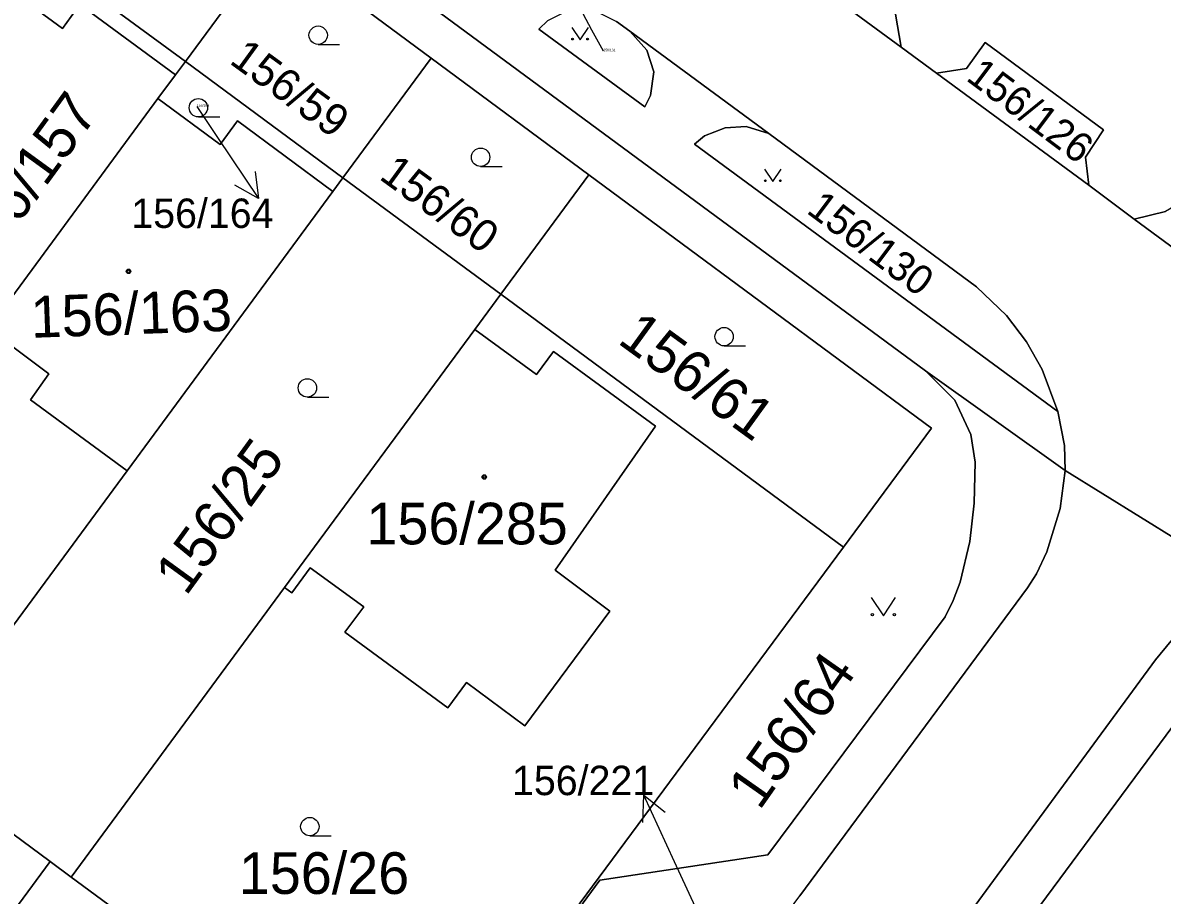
# Model space of a CAD drawing. Extents: x -598233 to -596890, y -1157848 to -1156431.
# Drawn here: x -597550.15 to -597503.64, y -1156840.44 to -1156804.85 of the extents above; entities that cross this region are included whole.
import ezdxf

# ---------------------------------------------------------------- set-up
doc = ezdxf.new("R2010")
doc.units = 0
for name, color, linetype in [('Level 1', 7, 'Continuous'), ('Level 4', 7, 'Continuous'), ('Level 5', 7, 'Continuous'), ('Level 57', 7, 'Continuous'), ('Level 60', 7, 'Continuous')]:
    doc.layers.add(name, color=color, linetype=linetype)

msp = doc.modelspace()

# ---------------------------------------------------------------- linework, layer by layer
at = {"layer": 'Level 1'}
for points in [[(-597675.04, -1156699.81), (-597644.05, -1156722.64), (-597605.82, -1156750.84), (-597563.45, -1156782.09), (-597513.3, -1156819.05)], [(-597514.3, -1156805.85), (-597514.52, -1156804.5), (-597514.27, -1156803.47), (-597508.33, -1156795.09), (-597496.6, -1156803.39), (-597502.59, -1156812.02), (-597503.51, -1156812.55), (-597504.78, -1156812.86)], [(-597539.9, -1156801.53), (-597543.51, -1156806.43)], [(-597539.9, -1156801.53), (-597533.48, -1156806.29)], [(-597543.51, -1156806.43), (-597549.95, -1156801.69)], [(-597514.3, -1156805.85), (-597518.43, -1156802.8)], [(-597551.07, -1156803.21), (-597548.53, -1156805.08), (-597547.82, -1156804.11), (-597543.91, -1156806.97)], [(-597525.37, -1156805.19), (-597524.67, -1156805.96), (-597524.39, -1156806.85), (-597524.53, -1156807.82), (-597524.76, -1156808.28), (-597529.08, -1156805.11), (-597528.72, -1156804.75), (-597527.9, -1156804.35), (-597526.79, -1156804.36), (-597525.92, -1156804.8)], [(-597525.92, -1156804.8), (-597525.37, -1156805.19)], [(-597519.7, -1156809.37), (-597525.37, -1156805.19)], [(-597512.85, -1156806.91), (-597511.63, -1156806.72), (-597510.87, -1156805.65), (-597506.04, -1156809.22), (-597506.77, -1156810.33), (-597506.64, -1156811.48)], [(-597512.85, -1156806.91), (-597514.3, -1156805.85)], [(-597543.51, -1156806.43), (-597543.91, -1156806.97)], [(-597537.08, -1156811.18), (-597543.51, -1156806.43)], [(-597533.48, -1156806.29), (-597537.08, -1156811.18)], [(-597533.48, -1156806.29), (-597527.04, -1156811.05)], [(-597544.63, -1156807.94), (-597543.91, -1156806.97)], [(-597506.64, -1156811.48), (-597512.85, -1156806.91)], [(-597552.26, -1156818.3), (-597544.63, -1156807.94)], [(-597537.49, -1156811.73), (-597541.38, -1156808.85), (-597542.09, -1156809.81), (-597544.63, -1156807.94)], [(-597519.7, -1156809.37), (-597520.62, -1156809.08), (-597521.48, -1156809.14), (-597522.32, -1156809.46), (-597522.73, -1156809.8), (-597507.9, -1156820.71)], [(-597507.9, -1156820.71), (-597508.54, -1156819), (-597509.18, -1156817.86), (-597509.99, -1156816.79), (-597511.22, -1156815.62), (-597519.7, -1156809.37)], [(-597537.49, -1156811.73), (-597537.08, -1156811.18)], [(-597530.64, -1156815.92), (-597537.08, -1156811.18)], [(-597530.64, -1156815.92), (-597527.04, -1156811.05)], [(-597527.04, -1156811.05), (-597513.06, -1156821.39), (-597516.65, -1156826.24)], [(-597545.89, -1156823.13), (-597537.49, -1156811.73)], [(-597504.78, -1156812.86), (-597506.64, -1156811.48)], [(-597500.61, -1156815.94), (-597504.78, -1156812.86)], [(-597531.7, -1156817.36), (-597530.64, -1156815.92)], [(-597516.65, -1156826.24), (-597530.64, -1156815.92)], [(-597531.7, -1156817.36), (-597529.18, -1156819.2), (-597528.48, -1156818.26), (-597524.32, -1156821.31), (-597528.42, -1156827.18), (-597526.19, -1156828.85), (-597529.65, -1156833.53), (-597532.04, -1156831.77), (-597532.8, -1156832.8), (-597537, -1156829.71), (-597536.23, -1156828.68), (-597538.41, -1156827.08), (-597539.17, -1156828.1), (-597539.46, -1156827.89)], [(-597539.46, -1156827.89), (-597531.7, -1156817.36)], [(-597552.26, -1156818.3), (-597552.14, -1156818.49), (-597551.38, -1156817.46), (-597549.08, -1156819.17), (-597549.83, -1156820.23), (-597545.89, -1156823.13)], [(-597549.31, -1156878.82), (-597548.81, -1156877.83), (-597548.51, -1156877.13), (-597548.17, -1156876.19), (-597548.03, -1156875.41), (-597548, -1156874.67), (-597548.22, -1156869.23), (-597526.59, -1156839.83), (-597519.73, -1156838.79), (-597512.5, -1156829.08), (-597512.17, -1156828.42), (-597511.88, -1156827.67), (-597511.49, -1156826.01), (-597511.31, -1156824.45), (-597511.28, -1156822.78), (-597511.45, -1156821.65), (-597512.11, -1156820.25), (-597513.3, -1156819.05)], [(-597513.3, -1156819.05), (-597507.6, -1156823.12)], [(-597507.6, -1156823.12), (-597507.63, -1156822.1), (-597507.9, -1156820.71)], [(-597554.61, -1156834.95), (-597545.89, -1156823.13)], [(-597507.6, -1156823.12), (-597507.81, -1156824.66), (-597508.35, -1156826.43), (-597508.77, -1156827.33), (-597509.14, -1156827.9), (-597518.43, -1156840.47)], [(-597507.6, -1156823.12), (-597499.92, -1156827.88)], [(-597534.23, -1156849.98), (-597516.65, -1156826.24)], [(-597548.17, -1156839.7), (-597539.46, -1156827.89)], [(-597514.13, -1156844.75), (-597503.91, -1156830.84), (-597503.28, -1156830.06), (-597502.2, -1156829.07), (-597500.85, -1156828.25), (-597499.92, -1156827.88)], [(-597502.47, -1156832.55), (-597511.93, -1156845.32), (-597510.88, -1156852.31), (-597512.21, -1156854.11)], [(-597554.61, -1156834.95), (-597549.03, -1156839.07)], [(-597566.94, -1156863.37), (-597549.03, -1156839.07)], [(-597549.03, -1156839.07), (-597548.17, -1156839.7)], [(-597548.17, -1156839.7), (-597534.23, -1156849.98)]]:
    msp.add_lwpolyline(points, dxfattribs=at)
at = {"layer": 'Level 5'}
for p, q in [((-597538.09, -1156805.73), (-597537.215, -1156805.73)), ((-597542.98, -1156808.69), (-597542.105, -1156808.69)), ((-597531.46, -1156810.71), (-597530.585, -1156810.71)), ((-597521.52, -1156818.03), (-597520.645, -1156818.03)), ((-597538.53, -1156820.12), (-597537.655, -1156820.12)), ((-597538.43, -1156838.02), (-597537.555, -1156838.02))]:
    msp.add_line(p, q, dxfattribs=at)
for points in [[(-597527.741, -1156805.04), (-597527.4, -1156805.55), (-597527.06, -1156805.04)], [(-597519.871, -1156810.82), (-597519.53, -1156811.33), (-597519.19, -1156810.82)], [(-597515.521, -1156828.3), (-597515.02, -1156829.05), (-597514.52, -1156828.3)]]:
    msp.add_lwpolyline(points, dxfattribs=at)
for centre, radius in [((-597538.09, -1156805.355), 0.375), ((-597527.706, -1156805.516), 0.034), ((-597527.095, -1156805.516), 0.034), ((-597542.98, -1156808.315), 0.375), ((-597531.46, -1156810.335), 0.375), ((-597519.836, -1156811.296), 0.034), ((-597519.225, -1156811.296), 0.034), ((-597545.83, -1156814.99), 0.09), ((-597545.83, -1156814.99), 0.0521), ((-597521.52, -1156817.655), 0.375), ((-597538.53, -1156819.745), 0.375), ((-597531.31, -1156823.38), 0.09), ((-597531.31, -1156823.38), 0.0521), ((-597515.47, -1156829), 0.05), ((-597514.571, -1156829), 0.05), ((-597538.43, -1156837.645), 0.375)]:
    msp.add_circle(centre, radius, dxfattribs=at)
at = {"layer": 'Level 57'}
for p, q in [((-597526.915, -1156805.144), (-597528.333, -1156802.5)), ((-597526.45, -1156806.01), (-597526.915, -1156805.144)), ((-597543.04, -1156808.27), (-597542.196, -1156809.529)), ((-597542.196, -1156809.529), (-597540.525, -1156812.02)), ((-597523.543, -1156839.083), (-597524.803, -1156836.36)), ((-597521.93, -1156842.57), (-597523.543, -1156839.083))]:
    msp.add_line(p, q, dxfattribs=at)
for points in [[(-597540.667, -1156810.911), (-597540.525, -1156812.02), (-597541.497, -1156811.468)], [(-597524.836, -1156837.478), (-597524.803, -1156836.36), (-597523.929, -1156837.058)]]:
    msp.add_lwpolyline(points, dxfattribs=at)
at = {"layer": 'Level 60'}
for points in [[(-597563.45, -1156782.09), (-597513.3, -1156819.05), (-597512.11, -1156820.25), (-597511.45, -1156821.65), (-597511.28, -1156822.78), (-597511.31, -1156824.45), (-597511.49, -1156826.01), (-597511.88, -1156827.67), (-597512.17, -1156828.42), (-597512.5, -1156829.08), (-597519.73, -1156838.79), (-597526.59, -1156839.83), (-597548.22, -1156869.23), (-597548, -1156874.67), (-597548.03, -1156875.41), (-597548.17, -1156876.19), (-597548.51, -1156877.13), (-597548.81, -1156877.83), (-597549.31, -1156878.82), (-597550.49, -1156878.9)], [(-597528.72, -1156804.75), (-597529.08, -1156805.11), (-597524.76, -1156808.28), (-597524.53, -1156807.82), (-597524.39, -1156806.85), (-597524.67, -1156805.96), (-597525.37, -1156805.19), (-597519.7, -1156809.37), (-597520.62, -1156809.08), (-597521.48, -1156809.14), (-597522.32, -1156809.46), (-597522.73, -1156809.8), (-597507.9, -1156820.71), (-597507.63, -1156822.1), (-597507.6, -1156823.12), (-597513.3, -1156819.05), (-597563.45, -1156782.09)], [(-597552.94, -1156875.36), (-597534.23, -1156849.98), (-597516.65, -1156826.24), (-597513.06, -1156821.39), (-597527.04, -1156811.05), (-597533.48, -1156806.29), (-597539.9, -1156801.53)], [(-597514.52, -1156804.5), (-597514.3, -1156805.85), (-597518.43, -1156802.8)], [(-597518.43, -1156802.8), (-597514.3, -1156805.85), (-597512.85, -1156806.91), (-597506.64, -1156811.48), (-597504.78, -1156812.86), (-597500.61, -1156815.94)], [(-597525.37, -1156805.19), (-597525.92, -1156804.8)], [(-597499.92, -1156827.88), (-597507.6, -1156823.12), (-597507.63, -1156822.1), (-597507.9, -1156820.71), (-597508.54, -1156819), (-597509.18, -1156817.86), (-597509.99, -1156816.79), (-597511.22, -1156815.62), (-597519.7, -1156809.37), (-597525.37, -1156805.19)], [(-597500.61, -1156815.94), (-597504.78, -1156812.86), (-597503.51, -1156812.55)], [(-597548.22, -1156869.23), (-597526.59, -1156839.83), (-597519.73, -1156838.79), (-597512.5, -1156829.08), (-597512.17, -1156828.42), (-597511.88, -1156827.67), (-597511.49, -1156826.01), (-597511.31, -1156824.45), (-597511.28, -1156822.78), (-597511.45, -1156821.65), (-597512.11, -1156820.25), (-597513.3, -1156819.05), (-597507.6, -1156823.12), (-597507.81, -1156824.66), (-597508.35, -1156826.43), (-597508.77, -1156827.33), (-597509.14, -1156827.9), (-597518.43, -1156840.47)], [(-597556.09, -1156891.33), (-597545.2, -1156876.63), (-597542.51, -1156873), (-597530.33, -1156856.54), (-597529.44, -1156855.36), (-597521.29, -1156844.33), (-597518.43, -1156840.47), (-597509.14, -1156827.9), (-597508.77, -1156827.33), (-597508.35, -1156826.43), (-597507.81, -1156824.66), (-597507.6, -1156823.12), (-597499.92, -1156827.88)], [(-597503.28, -1156830.06), (-597503.91, -1156830.84), (-597514.13, -1156844.75), (-597517.37, -1156849.16), (-597521.08, -1156854.14), (-597524.8, -1156859.17), (-597525.46, -1156860.06), (-597529.53, -1156865.6), (-597529.78, -1156865.9), (-597545, -1156886.43), (-597545.21, -1156886.71), (-597555.68, -1156900.85), (-597556.38, -1156901.73), (-597557.51, -1156903.08), (-597571.92, -1156909.74), (-597566.71, -1156912.01), (-597569.06, -1156913.87), (-597572.36, -1156916.15), (-597574.9, -1156917.73), (-597577.53, -1156919.24), (-597580.22, -1156920.61), (-597587.57, -1156923.77), (-597595.87, -1156927.27), (-597606.06, -1156931.56)], [(-597502.47, -1156832.55), (-597511.93, -1156845.32), (-597510.88, -1156852.31), (-597512.21, -1156854.11), (-597515.24, -1156858.2), (-597518.53, -1156862.64), (-597518.66, -1156862.82), (-597519.94, -1156864.55), (-597524.91, -1156871.25), (-597538.37, -1156889.43), (-597540.59, -1156888.01), (-597526.2, -1156868.54), (-597525.46, -1156867.77), (-597522.4, -1156863.62), (-597521.24, -1156861.81), (-597517.54, -1156856.8), (-597516.72, -1156855.92), (-597514.3, -1156852.69), (-597513.23, -1156851.2), (-597514.13, -1156844.75), (-597503.91, -1156830.84), (-597503.28, -1156830.06)], [(-597495.52, -1156866.88), (-597506.12, -1156872.11), (-597507.13, -1156871.36), (-597506.98, -1156871.16), (-597503.71, -1156866.74), (-597500.74, -1156862.59), (-597512.21, -1156854.11), (-597510.88, -1156852.31), (-597511.93, -1156845.32), (-597502.47, -1156832.55)]]:
    msp.add_lwpolyline(points, dxfattribs=at)
for points in [[(-597514.52, -1156804.5), (-597514.27, -1156803.47), (-597508.33, -1156795.09), (-597496.6, -1156803.39), (-597502.59, -1156812.02), (-597503.51, -1156812.55), (-597504.78, -1156812.86), (-597506.64, -1156811.48), (-597506.77, -1156810.33), (-597506.04, -1156809.22), (-597510.87, -1156805.65), (-597511.63, -1156806.72), (-597512.85, -1156806.91), (-597514.3, -1156805.85)], [(-597539.9, -1156801.53), (-597543.51, -1156806.43), (-597549.95, -1156801.69), (-597546.33, -1156796.78)], [(-597533.48, -1156806.29), (-597537.08, -1156811.18), (-597543.51, -1156806.43), (-597539.9, -1156801.53)], [(-597549.95, -1156801.69), (-597543.51, -1156806.43), (-597543.91, -1156806.97), (-597547.82, -1156804.11), (-597548.53, -1156805.08), (-597551.07, -1156803.21), (-597550.33, -1156802.21)], [(-597556.2, -1156815.43), (-597555.43, -1156814.37), (-597557.69, -1156812.71), (-597558.47, -1156813.76), (-597558.71, -1156813.58), (-597551.07, -1156803.21), (-597548.53, -1156805.08), (-597547.82, -1156804.11), (-597543.91, -1156806.97), (-597544.63, -1156807.94), (-597552.26, -1156818.3)], [(-597525.37, -1156805.19), (-597524.67, -1156805.96), (-597524.39, -1156806.85), (-597524.53, -1156807.82), (-597524.76, -1156808.28), (-597529.08, -1156805.11), (-597528.72, -1156804.75), (-597527.9, -1156804.35), (-597526.79, -1156804.36), (-597525.92, -1156804.8)], [(-597506.64, -1156811.48), (-597512.85, -1156806.91), (-597511.63, -1156806.72), (-597510.87, -1156805.65), (-597506.04, -1156809.22), (-597506.77, -1156810.33)], [(-597543.51, -1156806.43), (-597537.08, -1156811.18), (-597537.49, -1156811.73), (-597541.38, -1156808.85), (-597542.09, -1156809.81), (-597544.63, -1156807.94), (-597543.91, -1156806.97)], [(-597530.64, -1156815.92), (-597537.08, -1156811.18), (-597533.48, -1156806.29), (-597527.04, -1156811.05)], [(-597541.38, -1156808.85), (-597537.49, -1156811.73), (-597545.89, -1156823.13), (-597549.83, -1156820.23), (-597549.08, -1156819.17), (-597551.38, -1156817.46), (-597552.14, -1156818.49), (-597552.26, -1156818.3), (-597544.63, -1156807.94), (-597542.09, -1156809.81)], [(-597508.54, -1156819), (-597507.9, -1156820.71), (-597522.73, -1156809.8), (-597522.32, -1156809.46), (-597521.48, -1156809.14), (-597520.62, -1156809.08), (-597519.7, -1156809.37), (-597511.22, -1156815.62), (-597509.99, -1156816.79), (-597509.18, -1156817.86)], [(-597537.08, -1156811.18), (-597530.64, -1156815.92), (-597531.7, -1156817.36), (-597539.46, -1156827.89), (-597548.17, -1156839.7), (-597549.03, -1156839.07), (-597554.61, -1156834.95), (-597545.89, -1156823.13), (-597537.49, -1156811.73)], [(-597516.65, -1156826.24), (-597530.64, -1156815.92), (-597527.04, -1156811.05), (-597513.06, -1156821.39)], [(-597530.64, -1156815.92), (-597516.65, -1156826.24), (-597534.23, -1156849.98), (-597548.17, -1156839.7), (-597539.46, -1156827.89), (-597539.17, -1156828.1), (-597538.41, -1156827.08), (-597536.23, -1156828.68), (-597537, -1156829.71), (-597532.8, -1156832.8), (-597532.04, -1156831.77), (-597529.65, -1156833.53), (-597526.19, -1156828.85), (-597528.42, -1156827.18), (-597524.32, -1156821.31), (-597528.48, -1156818.26), (-597529.18, -1156819.2), (-597531.7, -1156817.36)], [(-597531.7, -1156817.36), (-597529.18, -1156819.2), (-597528.48, -1156818.26), (-597524.32, -1156821.31), (-597528.42, -1156827.18), (-597526.19, -1156828.85), (-597529.65, -1156833.53), (-597532.04, -1156831.77), (-597532.8, -1156832.8), (-597537, -1156829.71), (-597536.23, -1156828.68), (-597538.41, -1156827.08), (-597539.17, -1156828.1), (-597539.46, -1156827.89)], [(-597554.61, -1156834.95), (-597561.04, -1156830.21), (-597552.26, -1156818.3), (-597552.14, -1156818.49), (-597551.38, -1156817.46), (-597549.08, -1156819.17), (-597549.83, -1156820.23), (-597545.89, -1156823.13)], [(-597563.82, -1156828.16), (-597561.04, -1156830.21), (-597554.61, -1156834.95), (-597549.03, -1156839.07), (-597566.94, -1156863.37), (-597567.99, -1156862.6), (-597557.8, -1156848.71), (-597561.07, -1156846.27), (-597559.43, -1156844.05), (-597562.45, -1156841.83), (-597560.79, -1156839.52), (-597566.19, -1156835.53), (-597567.9, -1156837.83), (-597567.61, -1156838.03), (-597573.05, -1156845.4), (-597573.31, -1156845.17), (-597575.76, -1156848.47), (-597570.13, -1156852.62), (-597571.26, -1156854.14), (-597574.98, -1156859.11), (-597582.53, -1156853.54)], [(-597549.03, -1156839.07), (-597548.17, -1156839.7), (-597534.23, -1156849.98), (-597552.94, -1156875.36), (-597554.09, -1156874.51), (-597559.69, -1156870.38), (-597567.74, -1156864.45), (-597566.94, -1156863.37)]]:
    msp.add_lwpolyline(points, close=True, dxfattribs=at)

# ---------------------------------------------------------------- texts
at = {"layer": 'Level 4'}
for s, height, rotation, p in [('156/59', 1.3, 324, (-597541.759, -1156806.475)), ('156/126', 1.2, 323.1, (-597511.692, -1156807.164)), ('156/157', 1.7, 54, (-597551.832, -1156815.166)), ('156/60', 1.3, 324, (-597535.648, -1156811.193)), ('156/130', 1.2, 323.1, (-597518.202, -1156812.579)), ('156/163', 1.7, 2.0545, (-597549.797, -1156817.704)), ('156/61', 1.7, 324, (-597525.919, -1156817.889)), ('156/25', 1.7, 54, (-597543.484, -1156828.274)), ('156/64', 1.7, 54.9, (-597520.079, -1156837.019))]:
    msp.add_text(s, height=height, rotation=rotation, dxfattribs=at).set_placement(p)
for s, height, p in [('156/131', 0.1, (-597526.45, -1156806.01)), ('156/164', 0.1, (-597543.04, -1156808.27)), ('156/285', 1.7, (-597536.12, -1156826.13)), ('156/26', 1.7, (-597541.327, -1156840.39))]:
    msp.add_text(s, height=height, dxfattribs=at).set_placement(p)
at = {"layer": 'Level 57'}
for s, p in [('156/164', (-597545.715, -1156813.22)), ('156/221', (-597530.177, -1156836.36))]:
    msp.add_text(s, height=1.2, dxfattribs=at).set_placement(p)

doc.saveas('drawing.dxf')
